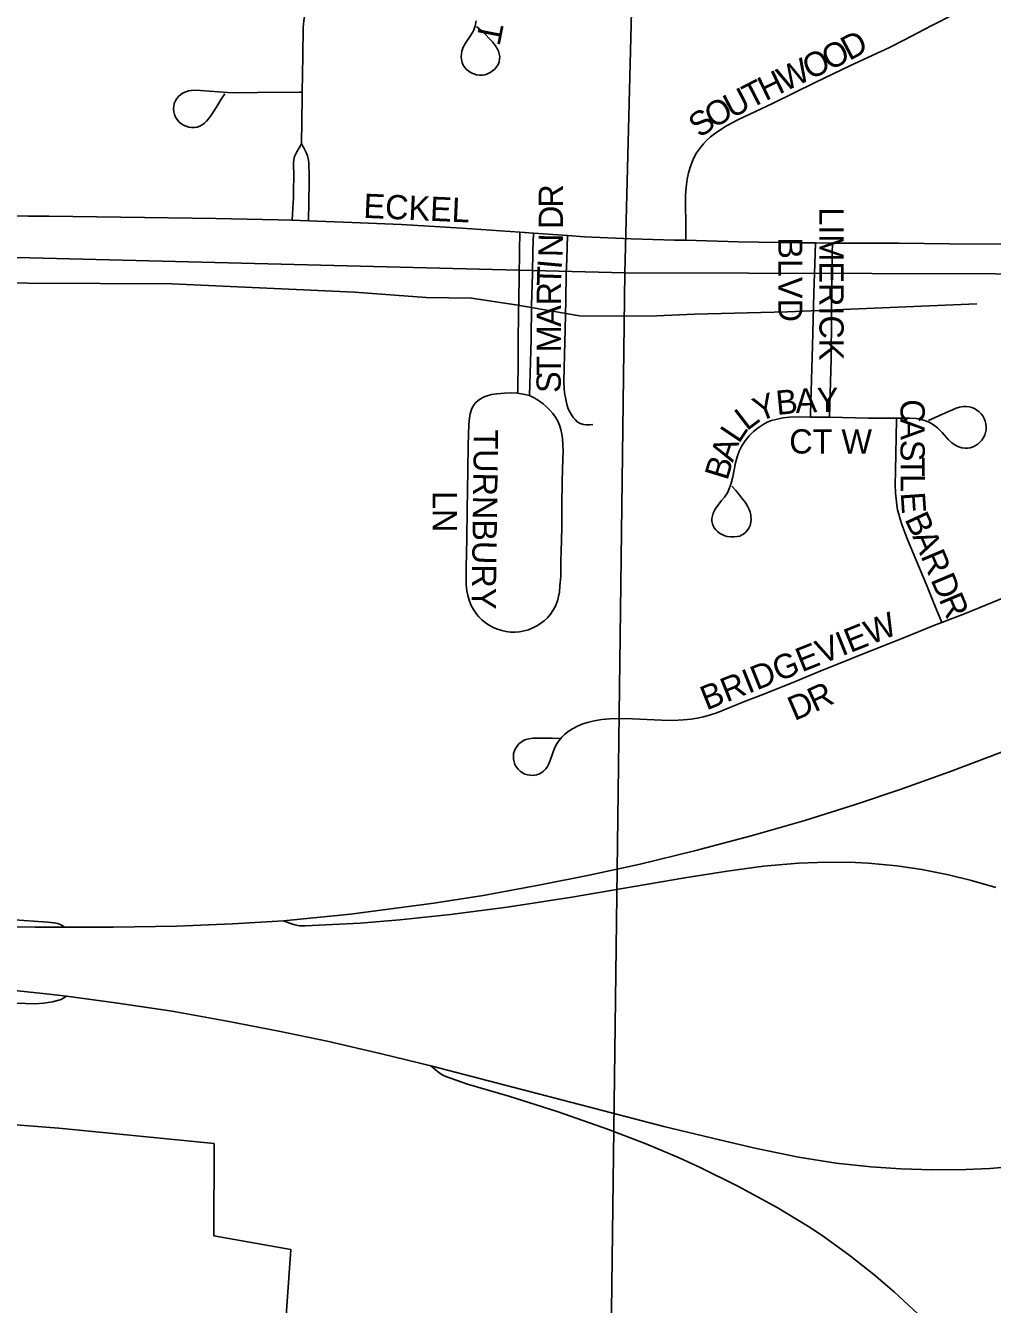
# Model space of a CAD drawing. Extents: x -5.6 to 34, y 0 to 22.
# Drawn here: x 4.822 to 5.62, y 18.084 to 19.139 of the extents above; entities that cross this region are included whole.
import ezdxf

# ---------------------------------------------------------------- set-up
doc = ezdxf.new("R2010")
doc.units = 0
for name, color, linetype in [('GM_X_City_Street', 7, 'Continuous'), ('GM_X_City_Street_Text', 7, 'Continuous'), ('GM_X_Interchange_Ramps', 7, 'Continuous'), ('GM_X_Interstate_Route', 7, 'Continuous'), ('GM_X_Minor_River', 7, 'Continuous'), ('GM_X_Section', 7, 'Continuous'), ('GM_X_Township_Road', 7, 'Continuous'), ('GM_X_US_Route', 7, 'Continuous')]:
    doc.layers.add(name, color=color, linetype=linetype)

msp = doc.modelspace()

# ---------------------------------------------------------------- linework, layer by layer
at = {"layer": 'GM_X_City_Street'}
for points in [[(5.0504, 19.0844), (5.051, 19.1141), (5.0512, 19.1378), (5.0516, 19.1432), (5.0524, 19.1485), (5.0533, 19.1525), (5.0546, 19.1565), (5.0563, 19.1602), (5.0591, 19.165), (5.0614, 19.1683), (5.064, 19.1715), (5.0679, 19.1753), (5.0721, 19.1788), (5.0754, 19.1812), (5.0801, 19.1839), (5.0907, 19.1893), (5.1214, 19.2043), (5.1426, 19.2149), (5.1599, 19.2234)], [(5.367, 18.9621), (5.367, 18.9688), (5.3668, 18.9992), (5.3673, 19.0059), (5.3681, 19.0125), (5.3692, 19.0178), (5.3707, 19.023), (5.3721, 19.0269), (5.3738, 19.0306), (5.3758, 19.0342), (5.3781, 19.0375), (5.3814, 19.0418), (5.3842, 19.0448), (5.3872, 19.0476), (5.3905, 19.0501), (5.3949, 19.0531), (5.4006, 19.0565), (5.41, 19.0614), (5.4385, 19.0749), (5.4738, 19.0924), (5.5022, 19.1061), (5.5213, 19.1149), (5.5344, 19.121), (5.5473, 19.1275), (5.5693, 19.139), (5.5885, 19.1488)], [(5.1941, 19.1386), (5.1983, 19.1349), (5.202, 19.1316), (5.2047, 19.1288), (5.2073, 19.1259), (5.21, 19.1225), (5.2113, 19.1204), (5.2123, 19.1182), (5.213, 19.116), (5.2134, 19.1137), (5.2133, 19.1115), (5.2129, 19.1093), (5.212, 19.1072), (5.2108, 19.1052), (5.2093, 19.1034), (5.2075, 19.1019), (5.2055, 19.1006), (5.2034, 19.0995), (5.2012, 19.0988), (5.1989, 19.0984), (5.1966, 19.0984), (5.1943, 19.0987), (5.192, 19.0994), (5.1898, 19.1003), (5.1878, 19.1016), (5.186, 19.1031), (5.1845, 19.1048), (5.1833, 19.1067), (5.1824, 19.1089), (5.1818, 19.1112), (5.1816, 19.1135), (5.1817, 19.1159), (5.1821, 19.1182), (5.1833, 19.1215), (5.1851, 19.1248), (5.1895, 19.1314), (5.1916, 19.1351), (5.1931, 19.139), (5.1939, 19.1432)], [(4.9865, 19.083), (4.9836, 19.0786), (4.9807, 19.074), (4.9773, 19.0686), (4.9748, 19.0646), (4.9729, 19.0623), (4.9715, 19.0604), (4.9698, 19.0587), (4.9679, 19.0574), (4.9658, 19.0563), (4.9636, 19.0556), (4.9614, 19.0552), (4.959, 19.0552), (4.9567, 19.0555), (4.9545, 19.0562), (4.9523, 19.0572), (4.9503, 19.0585), (4.9486, 19.06), (4.9471, 19.0618), (4.9459, 19.0638), (4.945, 19.0659), (4.9444, 19.0682), (4.9442, 19.0705), (4.9443, 19.0728), (4.9448, 19.0751), (4.9457, 19.0772), (4.9469, 19.0792), (4.9484, 19.0809), (4.9502, 19.0824), (4.9522, 19.0837), (4.9543, 19.0847), (4.9566, 19.0854), (4.9589, 19.0858), (4.9614, 19.086), (4.9665, 19.0858), (4.9888, 19.084), (4.9968, 19.0837), (5.0135, 19.084), (5.0482, 19.0844), (5.0504, 19.0844)], [(5.0498, 19.0418), (5.0503, 19.0799), (5.0504, 19.0844)], [(5.0422, 18.9786), (5.043, 18.9935), (5.0431, 18.9962), (5.0433, 19.004), (5.0435, 19.0145), (5.0433, 19.0259), (5.0434, 19.0289), (5.044, 19.0314), (5.0458, 19.035), (5.0498, 19.0418)], [(5.0555, 18.9782), (5.0557, 18.9938), (5.056, 19.0103), (5.056, 19.0175), (5.0559, 19.0235), (5.0558, 19.0264), (5.0554, 19.0295), (5.0547, 19.0319), (5.0535, 19.0346), (5.0516, 19.0383), (5.0498, 19.0418)], [(4.9006, 18.9811), (4.9792, 18.9801), (5.0305, 18.979), (5.0422, 18.9786)], [(5.0422, 18.9786), (5.0555, 18.9782)], [(5.0555, 18.9782), (5.0912, 18.9769), (5.1322, 18.9751), (5.1822, 18.9722), (5.2299, 18.9688)], [(5.2281, 18.8358), (5.2282, 18.8385), (5.2285, 18.8626), (5.2287, 18.8806), (5.2289, 18.8997), (5.2295, 18.9308), (5.2297, 18.9534), (5.2299, 18.9688)], [(5.2299, 18.9688), (5.2412, 18.968)], [(5.2379, 18.834), (5.2389, 18.8616), (5.2392, 18.8804), (5.2397, 18.9082), (5.2403, 18.9343), (5.2408, 18.9534), (5.2412, 18.968)], [(5.2412, 18.968), (5.2413, 18.968), (5.2694, 18.9661)], [(5.2901, 18.81), (5.2875, 18.8098), (5.2848, 18.8098), (5.2824, 18.8101), (5.2797, 18.811), (5.2774, 18.8123), (5.2755, 18.8141), (5.2742, 18.8156), (5.2725, 18.818), (5.2711, 18.8205), (5.2699, 18.8231), (5.269, 18.8257), (5.2681, 18.8293), (5.2676, 18.8323), (5.2669, 18.8361), (5.2665, 18.8399), (5.2663, 18.8452), (5.2668, 18.8676), (5.2673, 18.8887), (5.2679, 18.9124), (5.2683, 18.9348), (5.2687, 18.9466), (5.2694, 18.9661)], [(5.2694, 18.9661), (5.2834, 18.9651), (5.3218, 18.9633), (5.3575, 18.9623), (5.367, 18.9621)], [(5.367, 18.9621), (5.4102, 18.9609), (5.4605, 18.9601), (5.474, 18.96)], [(5.4698, 18.8161), (5.4698, 18.8185), (5.471, 18.8566), (5.4714, 18.875), (5.4726, 18.9185), (5.4737, 18.951), (5.474, 18.96)], [(5.474, 18.96), (5.4879, 18.9598)], [(5.4855, 18.816), (5.4869, 18.8644), (5.4873, 18.8983), (5.4878, 18.9514), (5.4879, 18.9598)], [(5.4879, 18.9598), (5.5036, 18.9596), (5.5431, 18.9597), (5.5844, 18.9592), (5.6459, 18.9588)], [(5.2281, 18.8358), (5.2227, 18.8362), (5.2173, 18.8358), (5.211, 18.8353), (5.2065, 18.8347), (5.2029, 18.8338), (5.2006, 18.833), (5.1974, 18.8313), (5.1955, 18.8299), (5.1937, 18.8283), (5.1923, 18.8265), (5.191, 18.8245), (5.19, 18.8224), (5.189, 18.8189), (5.1884, 18.8152), (5.1879, 18.8101), (5.1873, 18.7931), (5.187, 18.7721), (5.1866, 18.7393), (5.1862, 18.7157), (5.1856, 18.6921), (5.1856, 18.6829), (5.1857, 18.6778), (5.1863, 18.6727), (5.187, 18.669), (5.1884, 18.6642), (5.1898, 18.6607), (5.1916, 18.6574), (5.1944, 18.6533), (5.196, 18.6514), (5.1986, 18.6488), (5.2015, 18.6464), (5.2046, 18.6444), (5.2079, 18.6426), (5.2114, 18.6411), (5.215, 18.64), (5.2186, 18.6392), (5.2223, 18.6387), (5.2261, 18.6387), (5.2298, 18.639), (5.2335, 18.6397), (5.2371, 18.6407), (5.2406, 18.6421), (5.2439, 18.6438), (5.2471, 18.6458), (5.25, 18.6481), (5.2528, 18.6506), (5.2552, 18.6534), (5.2573, 18.6565), (5.2591, 18.6597), (5.261, 18.6644), (5.2619, 18.668), (5.2626, 18.6717), (5.2631, 18.6768), (5.2637, 18.6847), (5.2639, 18.6977), (5.2641, 18.7056), (5.2643, 18.7147), (5.2645, 18.7252), (5.2647, 18.7436), (5.265, 18.7633), (5.2655, 18.7817), (5.2656, 18.7882), (5.2655, 18.7933), (5.2651, 18.7984), (5.2646, 18.8022), (5.2638, 18.8059), (5.2626, 18.8094), (5.2612, 18.8128), (5.2594, 18.8161), (5.2572, 18.8192), (5.2548, 18.822), (5.2521, 18.8246), (5.2492, 18.827), (5.2454, 18.83), (5.2419, 18.832), (5.2379, 18.834)], [(5.2379, 18.834), (5.2327, 18.8352), (5.2282, 18.8358), (5.2281, 18.8358)], [(5.5408, 18.8152), (5.5517, 18.8153), (5.5571, 18.8149), (5.5611, 18.8142), (5.5638, 18.8135), (5.5677, 18.812), (5.5714, 18.8099), (5.5747, 18.8073), (5.5785, 18.8034), (5.5836, 18.7975), (5.5864, 18.795), (5.5883, 18.7936), (5.5914, 18.7919), (5.5948, 18.7908), (5.5971, 18.7906), (5.5995, 18.7905), (5.6017, 18.7909), (5.604, 18.7916), (5.606, 18.7926), (5.608, 18.7939), (5.6097, 18.7955), (5.6113, 18.7972), (5.6126, 18.7992), (5.6136, 18.8013), (5.6143, 18.8035), (5.6147, 18.8058), (5.6148, 18.8082), (5.6146, 18.8105), (5.614, 18.8128), (5.6132, 18.815), (5.6121, 18.8171), (5.6107, 18.8189), (5.609, 18.8205), (5.6071, 18.822), (5.6051, 18.8232), (5.603, 18.824), (5.6007, 18.8246), (5.5984, 18.8248), (5.596, 18.8248), (5.5929, 18.8243), (5.5901, 18.8235), (5.5869, 18.8221), (5.5838, 18.8207), (5.5807, 18.8193), (5.5764, 18.8174), (5.5726, 18.8158), (5.5672, 18.8134)], [(5.405, 18.7591), (5.4081, 18.7556), (5.4107, 18.7525), (5.4133, 18.7492), (5.4158, 18.7459), (5.4176, 18.7431), (5.4193, 18.7399), (5.4201, 18.7377), (5.4205, 18.7356), (5.4207, 18.734), (5.4209, 18.7318), (5.4207, 18.7295), (5.42, 18.7267), (5.419, 18.7246), (5.4177, 18.7225), (5.4164, 18.7212), (5.4152, 18.7202), (5.4141, 18.7194), (5.4133, 18.7189), (5.4114, 18.718), (5.4092, 18.7176), (5.4066, 18.7173), (5.4042, 18.7173), (5.4011, 18.7177), (5.399, 18.7183), (5.3969, 18.7192), (5.3948, 18.7203), (5.3932, 18.7217), (5.3916, 18.7232), (5.3902, 18.7249), (5.3897, 18.7259), (5.3889, 18.728), (5.3885, 18.7302), (5.3885, 18.7325), (5.3889, 18.7348), (5.3896, 18.737), (5.3912, 18.7402), (5.3934, 18.7432), (5.3965, 18.7472), (5.3988, 18.7501), (5.4013, 18.7537), (5.4031, 18.7577), (5.4045, 18.7616), (5.4058, 18.7669), (5.408, 18.7785), (5.4092, 18.7833), (5.411, 18.788), (5.4133, 18.7925), (5.416, 18.7967), (5.4192, 18.8006), (5.4227, 18.8042), (5.4266, 18.8074), (5.4308, 18.8101), (5.4341, 18.8119), (5.4376, 18.8133), (5.4424, 18.8146), (5.4474, 18.8156), (5.4524, 18.8161), (5.4589, 18.8163), (5.4698, 18.8161)], [(5.4698, 18.8161), (5.477, 18.8161), (5.4855, 18.816)], [(5.4855, 18.816), (5.5176, 18.8153), (5.5385, 18.8152), (5.5408, 18.8152)], [(5.5781, 18.6466), (5.5723, 18.6611), (5.5656, 18.6778), (5.5553, 18.7019), (5.5494, 18.7165), (5.5453, 18.7275), (5.5438, 18.732), (5.5426, 18.7361), (5.5417, 18.7397), (5.541, 18.7436), (5.5404, 18.7487), (5.5399, 18.7538), (5.5397, 18.7602), (5.5399, 18.7719), (5.5408, 18.8139), (5.5408, 18.8152)], [(5.5781, 18.6466), (5.5984, 18.6544), (5.6567, 18.6783)], [(5.2627, 18.5508), (5.2566, 18.5511), (5.2527, 18.5512), (5.2486, 18.5513), (5.2447, 18.5513), (5.241, 18.5511), (5.2374, 18.5506), (5.235, 18.55), (5.2329, 18.5492), (5.231, 18.548), (5.2292, 18.5464), (5.2277, 18.5447), (5.2264, 18.5427), (5.2255, 18.5406), (5.2248, 18.5384), (5.2246, 18.5361), (5.2247, 18.5337), (5.2252, 18.5315), (5.2259, 18.5293), (5.2271, 18.5273), (5.2285, 18.5255), (5.2302, 18.5239), (5.2321, 18.5226), (5.2342, 18.5215), (5.2365, 18.5208), (5.2387, 18.5205), (5.2411, 18.5204), (5.2436, 18.5208), (5.2456, 18.5214), (5.2482, 18.5228), (5.2495, 18.5238), (5.2513, 18.5258), (5.2525, 18.5273), (5.2535, 18.5294), (5.255, 18.5328), (5.2571, 18.539), (5.2587, 18.5429), (5.2605, 18.5465), (5.2621, 18.5489), (5.2646, 18.5521), (5.2667, 18.5541), (5.2699, 18.5566), (5.2733, 18.5589), (5.2782, 18.5614), (5.282, 18.5629), (5.2859, 18.5641), (5.2912, 18.5654), (5.2977, 18.5665), (5.3042, 18.5671), (5.3122, 18.5674), (5.3229, 18.5671), (5.3468, 18.5659), (5.3559, 18.5658), (5.3649, 18.5662), (5.3714, 18.5668), (5.3764, 18.5676), (5.3814, 18.5687), (5.3864, 18.5701), (5.3924, 18.5722), (5.4155, 18.5814), (5.429, 18.5866), (5.4546, 18.5969), (5.4764, 18.606), (5.5032, 18.6167), (5.5093, 18.6192), (5.5459, 18.6338), (5.5715, 18.6441), (5.5781, 18.6466)]]:
    msp.add_lwpolyline(points, dxfattribs=at)
at = {"layer": 'GM_X_Interchange_Ramps'}
for points in [[(4.8543, 18.3952), (4.8515, 18.3971), (4.8487, 18.3981), (4.8455, 18.3988), (4.8404, 18.3994), (4.8089, 18.4015)], [(4.8063, 18.3327), (4.8296, 18.3318), (4.8372, 18.3325), (4.8442, 18.3335), (4.8515, 18.3356), (4.8558, 18.3381)]]:
    msp.add_lwpolyline(points, dxfattribs=at)
at = {"layer": 'GM_X_Interstate_Route'}
for points in [[(5.6229, 18.4278), (5.6028, 18.4338), (5.5836, 18.4385), (5.5618, 18.4428), (5.541, 18.4459), (5.5175, 18.448), (5.5017, 18.4487), (5.4755, 18.4486), (5.4598, 18.4479), (5.431, 18.4454), (5.401, 18.4415), (5.366, 18.436), (5.2728, 18.4198), (5.2196, 18.4117), (5.1727, 18.4055), (5.1309, 18.4011), (5.0982, 18.3986), (5.0527, 18.3962), (5.048, 18.3963), (5.0444, 18.397), (5.0414, 18.3978), (5.0348, 18.4003)], [(5.0348, 18.4003), (4.9929, 18.3978), (4.9469, 18.3961), (4.8944, 18.3952), (4.8543, 18.3952), (4.83, 18.3953), (4.7433, 18.3966), (4.6645, 18.3979), (4.57, 18.3992), (4.444, 18.4014), (4.2499, 18.4038)], [(5.5583, 18.0761), (5.5391, 18.094), (5.5221, 18.1085), (5.5025, 18.124), (5.4802, 18.1401), (5.4681, 18.1481), (5.4422, 18.1637), (5.41, 18.1814), (5.3783, 18.1972), (5.3615, 18.2048), (5.3349, 18.2161), (5.303, 18.2283), (5.2608, 18.2429), (5.2208, 18.2558), (5.1869, 18.2656), (5.1688, 18.272), (5.1665, 18.273), (5.1642, 18.2745), (5.1617, 18.2764), (5.1565, 18.2807), (5.1157, 18.2906), (5.0709, 18.3011), (5.031, 18.3094), (4.9884, 18.3177), (4.9431, 18.3257), (4.8963, 18.3328), (4.8558, 18.3381), (4.8416, 18.34), (4.7919, 18.3452)]]:
    msp.add_lwpolyline(points, dxfattribs=at)
at = {"layer": 'GM_X_Minor_River'}
for points in [[(4.7649, 18.927), (4.9429, 18.9261), (5.0936, 18.9193), (5.1526, 18.915), (5.1901, 18.9143), (5.2267, 18.9088), (5.2792, 18.8998), (5.3367, 18.8995), (5.3742, 18.9012), (5.4509, 18.903)], [(5.4509, 18.903), (5.6072, 18.9098)], [(4.3284, 18.08), (4.4129, 18.1108), (4.4615, 18.1377), (4.5022, 18.1688), (4.5347, 18.1913), (4.5769, 18.2223), (4.6283, 18.2315), (4.7115, 18.2399), (4.8494, 18.2293), (4.9776, 18.2166), (4.9773, 18.1404), (5.0409, 18.1292), (5.0324, 18.0083)]]:
    msp.add_lwpolyline(points, dxfattribs=at)
at = {"layer": 'GM_X_Section'}
for points in [[(7.5006, 20.9), (7.2498, 20.9), (7.2609, 20.8761), (5.343, 19.9706), (5.3166, 18.9352), (7.4578, 18.9294)], [(3.2183, 20.0634), (4.4924, 20.0538), (4.6881, 19.6534), (5.343, 19.9706), (5.3166, 18.9352), (3.1889, 18.9888)], [(3.1889, 18.9888), (5.3166, 18.9352), (5.2895, 16.8144), (3.1401, 16.8587)], [(5.3166, 18.9352), (7.4578, 18.9294), (7.4183, 16.7871), (5.2895, 16.8144)]]:
    msp.add_lwpolyline(points, close=True, dxfattribs=at)
at = {"layer": 'GM_X_Township_Road'}
for points in [[(4.7719, 18.9824), (4.8245, 18.982)], [(4.8245, 18.982), (4.8392, 18.9819)], [(4.8392, 18.9819), (4.8413, 18.9819), (4.9006, 18.9811)]]:
    msp.add_lwpolyline(points, dxfattribs=at)
at = {"layer": 'GM_X_US_Route'}
for points in [[(5.6275, 18.5397), (5.5846, 18.5234), (5.5438, 18.5087), (5.5077, 18.4966), (5.4651, 18.4833), (5.421, 18.4706), (5.374, 18.4581), (5.3294, 18.4473), (5.2871, 18.4381), (5.2469, 18.4301), (5.1996, 18.4214), (5.1591, 18.415), (5.0902, 18.4058), (5.0348, 18.4003)], [(5.6464, 18.1984), (5.6177, 18.196), (5.5981, 18.1951), (5.5706, 18.1949), (5.5445, 18.1956), (5.5197, 18.1974), (5.491, 18.2004), (5.46, 18.2054), (5.4253, 18.2125), (5.3947, 18.2195), (5.3488, 18.2307), (5.2929, 18.2453), (5.1565, 18.2807)]]:
    msp.add_lwpolyline(points, dxfattribs=at)

# ---------------------------------------------------------------- texts
at = {"layer": 'GM_X_City_Street_Text'}
for s, rotation, p in [('T', 258.8669, (5.197, 19.1431)), ('D', 27.9101, (5.5018, 19.11)), ('O', 25.314, (5.4692, 19.0943)), ('O', 25.9154, (5.4853, 19.1019)), ('W', 25.3318, (5.4485, 19.0845)), ('T', 27.2369, (5.4203, 19.0704)), ('H', 25.9492, (5.4327, 19.0768)), ('U', 27.3666, (5.4047, 19.0624)), ('O', 28.2756, (5.3892, 19.0541)), ('S', 37.0338, (5.3787, 19.046)), ('ECKEL', 357.456, (5.1006, 18.9807)), ('R', 90, (5.2655, 18.989)), ('D', 90, (5.2655, 18.9714)), ('LIMERICK', 270, (5.4772, 18.9893)), ('N', 88.9343, (5.2652, 18.9481)), ('BLVD', 270, (5.4432, 18.9646)), ('T', 88.1691, (5.2639, 18.924)), ('I', 84.8807, (5.2643, 18.9378)), ('R', 89.9028, (5.2639, 18.9083)), ('A', 89.9126, (5.2638, 18.8907)), ('M', 89.9196, (5.2638, 18.8696)), ('T', 89.918, (5.2638, 18.8502)), ('S', 89.918, (5.2637, 18.8361)), ('Y', 20.7095, (5.4271, 18.812)), ('B', 5.5704, (5.4422, 18.8179)), ('A', 2.9737, (5.4577, 18.8194)), ('Y', 0.7651, (5.4751, 18.8203)), ('L', 37.4437, (5.4173, 18.8042)), ('C', 270.0729, (5.5441, 18.8309)), ('A', 270.0656, (5.5441, 18.815)), ('TURNBURY', 269.2458, (5.1921, 18.8062)), ('L', 56.3781, (5.4107, 18.7937)), ('CT W', 0, (5.4523, 18.7861)), ('A', 71.5858, (5.4057, 18.7783)), ('S', 270.0705, (5.5441, 18.7974)), ('B', 73.124, (5.4012, 18.7632)), ('T', 270.082, (5.5441, 18.7833)), ('L', 270.0547, (5.5442, 18.7693)), ('LN', 270, (5.158, 18.7552)), ('E', 274.0056, (5.5442, 18.7537)), ('B', 294.7218, (5.5472, 18.732)), ('A', 292.7796, (5.5537, 18.7178)), ('R', 292.8014, (5.5605, 18.7016)), ('D', 292.7796, (5.5687, 18.6821)), ('R', 292.8014, (5.5755, 18.6659)), ('BRIDGEVIEW', 21.8019, (5.384, 18.5739)), ('D', 23.2015, (5.4566, 18.5652)), ('R', 24.6517, (5.4733, 18.5724))]:
    msp.add_text(s, height=0.02, rotation=rotation, dxfattribs=at).set_placement(p)

doc.saveas('drawing.dxf')
